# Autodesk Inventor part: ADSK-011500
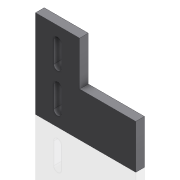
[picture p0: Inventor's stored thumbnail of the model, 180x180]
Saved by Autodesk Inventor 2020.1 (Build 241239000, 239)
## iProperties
Created: 2000-02
Part Number: ADSK-011500
Material: RA HRS
Document SubType Name: Modeling
Designer: sspink
Density: 7.83 g/cm^3
Appearance: Métal - Acier
Mass: 621.684 g
Surface Area: 218.05 cm^2
Volume: 79.3977 cm^3
Control State: 0
Checked Out: False
Master: False
Shininess: 0.0
Length Units: 11269
Angle Units: 11279
Time Units: 11290
Mass Units: 11283
Length Display Precision: 3
Angle Display Precision: 2
Compacted: True
Cutlength: 4.56
Material Desc: FLAT,HRS,0.375 X 4.00
Material_number: A084411
Dimensions: 116x102x10 mm
Mass: 0,622 kg
Density: 0.0
Volumn: 0.0
Area: 0.0
PropertySet Name: Model Information
Author: sspink
Revision Number: -
Title: ADSK-011500
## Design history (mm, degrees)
sketch "Sketch3"
  geometry: L1 (51, 102)-(0, 102) reference; L2 (30, 16)-(21, 16); L3 (21, 16)-(21, 41); L4 (21, 41)-(30, 41); L5 (30, 41)-(30, 16); L6 (30, 61)-(21, 61); L7 (21, 61)-(21, 86); L8 (21, 86)-(30, 86); L9 (30, 86)-(30, 61); A1 r 4.5 centre (25.5, 86) between (30, 86) and (21, 86); A2 r 4.5 centre (25.5, 61) between (21, 61) and (30, 61); A3 r 4.5 centre (25.5, 16) between (21, 16) and (30, 16); A4 r 4.5 centre (25.5, 41) between (30, 41) and (21, 41); 2 further points
  constraints: 16 end point, 8 point on circle, 4 centre point, 4 parallel, 4 tangent, 2 equal length, 2 horizontal, 2 midpoint, 2 perpendicular, 2 vertical alignment
  dimensions: "d7" = 25 distance of L6.end L7.end; "d8" = 9 distance of L7.end L8.end; "d10" = 16 distance from line of A1.centre L1; "d14" = 45 distance between parallel lines of L4 L8
node "Extrusion3" dims "d12" = 50.8, "d13" = 0
workplane "Arbeitsebene1"
node "Solide1"
  node "Extrusion1" dims "d2" = 10, "d3" = 0
  node "Extrusion2" dims "d5" = 51, "d6" = 0
sketch "Sketch1"
  geometry: L1 (0, 0)-(116, 0); L2 (116, 0)-(116, 51); L3 (116, 51)-(0, 51); L4 (0, 51)-(0, 0)
  constraints: 8 end point, 2 parallel, 1 horizontal, 1 perpendicular
  dimensions: "d0" = 51 distance between parallel lines of L1 L3; "d1" = 116 distance between parallel lines of L2 L4
sketch "Sketch2"
  geometry: L1 (0, -10)-(116, -10) reference; L2 (116, 0)-(0, 0) reference; L3 (0, 0)-(0, -10) reference; L4 (51, -10)-(51, 0)
  constraints: 2 end point, 2 point on line, 1 perpendicular
  dimensions: "d4" = 51 distance between parallel lines of L4 L3
node "Corps solides"
node "Corps surfaciques"
